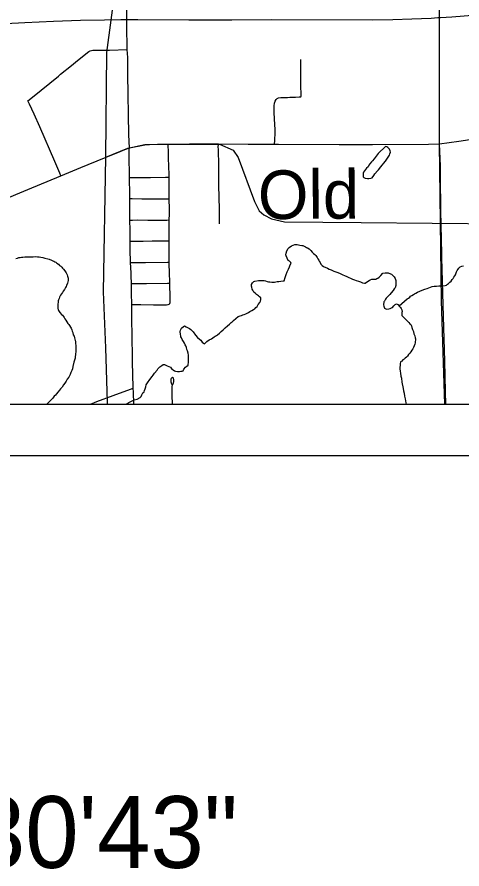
# Model space of a CAD drawing. Extents: x 0 to 34, y 0 to 22.
# Drawn here: x 6.813 to 7.681, y 13.194 to 14.854 of the extents above; entities that cross this region are included whole.
import ezdxf

# ---------------------------------------------------------------- set-up
doc = ezdxf.new("R2010")
doc.units = 0
for name, color, linetype in [('GM_X_City_Street', 7, 'Continuous'), ('GM_X_Corporation', 7, 'Continuous'), ('GM_X_County_Road', 7, 'Continuous'), ('GM_X_Interstate_Route', 7, 'Continuous'), ('GM_X_Minor_Lake', 7, 'Continuous'), ('GM_X_Minor_River', 7, 'Continuous'), ('GM_X_Minor_River_Text', 7, 'Continuous'), ('GM_X_Rail_Line', 7, 'Continuous'), ('GM_X_State_Route', 7, 'Continuous'), ('GM_X_Township_Road', 7, 'Continuous'), ('SH_Data', 7, 'Continuous'), ('SH_Text', 7, 'Continuous')]:
    doc.layers.add(name, color=color, linetype=linetype)

msp = doc.modelspace()

# ---------------------------------------------------------------- linework, layer by layer
at = {"layer": 'GM_X_City_Street'}
for points in [[(6.8345, 14.6908), (6.8433, 14.6982), (6.8942, 14.7392), (6.8984, 14.7429), (6.9194, 14.7598), (6.9314, 14.7696), (6.9434, 14.7796), (6.9506, 14.7854), (6.9531, 14.787), (6.9557, 14.7882), (6.9582, 14.789), (6.9609, 14.7896), (6.9639, 14.7899), (6.9893, 14.7899), (6.9933, 14.7899), (7.028, 14.7908)], [(7.3155, 14.6063), (7.3157, 14.614), (7.3163, 14.6296), (7.3162, 14.6354), (7.3158, 14.645), (7.3148, 14.6679), (7.3146, 14.6743), (7.3148, 14.6779), (7.3146, 14.6813), (7.3151, 14.6868), (7.3164, 14.6905), (7.3184, 14.6934), (7.3204, 14.6954), (7.3232, 14.6967), (7.3276, 14.6977), (7.3406, 14.6978), (7.3448, 14.6979), (7.3517, 14.6981), (7.3564, 14.6984), (7.3634, 14.6987), (7.3654, 14.6988), (7.3663, 14.699), (7.3671, 14.6999), (7.3671, 14.7022), (7.3667, 14.7217), (7.3665, 14.75), (7.3667, 14.7715)], [(6.8986, 14.5448), (6.8965, 14.5499), (6.8873, 14.5728), (6.858, 14.6401), (6.8468, 14.6652), (6.8377, 14.6846), (6.8345, 14.6908)], [(7.0323, 14.5995), (7.0624, 14.605), (7.0717, 14.6059), (7.0872, 14.6066), (7.1079, 14.6067), (7.1119, 14.6069), (7.1492, 14.607), (7.1926, 14.607), (7.2059, 14.6072), (7.2636, 14.6066), (7.3155, 14.6063), (7.3228, 14.6063), (7.4411, 14.6057), (7.5065, 14.606), (7.6155, 14.6069), (7.6368, 14.607)], [(7.1109, 14.2958), (7.1115, 14.2963), (7.1118, 14.2983), (7.1121, 14.3065), (7.1111, 14.3356), (7.1111, 14.3406), (7.1107, 14.3527), (7.1102, 14.3769), (7.1101, 14.4019), (7.1097, 14.4183), (7.1098, 14.4305), (7.1101, 14.4544), (7.1101, 14.4589), (7.1106, 14.4701), (7.1104, 14.4885), (7.1102, 14.4916), (7.11, 14.5001), (7.1096, 14.5315), (7.1098, 14.5422), (7.1091, 14.5684), (7.1087, 14.5745), (7.1088, 14.5774), (7.1084, 14.5956), (7.1081, 14.6005), (7.1079, 14.6067)], [(7.2081, 14.4516), (7.2077, 14.4796), (7.2069, 14.5262), (7.2065, 14.551), (7.2065, 14.5725), (7.2061, 14.5881), (7.2061, 14.5973), (7.2057, 14.6003), (7.2059, 14.6072)], [(7.0324, 14.5415), (7.0367, 14.5417), (7.0429, 14.5417), (7.0621, 14.5415), (7.0736, 14.5416), (7.1028, 14.5421), (7.1098, 14.5422)], [(7.0334, 14.5005), (7.038, 14.5004), (7.0567, 14.5), (7.082, 14.5), (7.1009, 14.4998), (7.104, 14.4999), (7.11, 14.5001)], [(7.0335, 14.4585), (7.0383, 14.4586), (7.0477, 14.4588), (7.0685, 14.4587), (7.1053, 14.4587), (7.1101, 14.4589)], [(7.0339, 14.4176), (7.0452, 14.4176), (7.0591, 14.4178), (7.0766, 14.4179), (7.0973, 14.418), (7.1032, 14.418), (7.1097, 14.4183)], [(7.0348, 14.3758), (7.0393, 14.3758), (7.0477, 14.3757), (7.0637, 14.3761), (7.1068, 14.3768), (7.1102, 14.3769)], [(7.0364, 14.3349), (7.0417, 14.335), (7.066, 14.3353), (7.1068, 14.3357), (7.1111, 14.3356)], [(7.0369, 14.2941), (7.0544, 14.2939), (7.0793, 14.2937), (7.1009, 14.2937), (7.1048, 14.2937), (7.1082, 14.2941), (7.1097, 14.2949), (7.1109, 14.2958)], [(7.1162, 14.1), (7.1159, 14.1171), (7.1159, 14.121), (7.1158, 14.1313), (7.1157, 14.1342), (7.1159, 14.1358), (7.1163, 14.1371), (7.1168, 14.1384), (7.1176, 14.1396), (7.1182, 14.1407), (7.1186, 14.1422), (7.1188, 14.1435), (7.119, 14.1447), (7.119, 14.1466), (7.1189, 14.1478), (7.1186, 14.1493), (7.1182, 14.1504), (7.1175, 14.1511), (7.1167, 14.1515), (7.1157, 14.1515), (7.1148, 14.1512), (7.1139, 14.1497), (7.1134, 14.1485), (7.1131, 14.1459), (7.1133, 14.1434), (7.1139, 14.1413), (7.1157, 14.1369)], [(6.9564, 14.1), (6.9564, 14.1), (6.9691, 14.1049), (7.0009, 14.1169), (7.0348, 14.1293), (7.0399, 14.1312)]]:
    msp.add_lwpolyline(points, dxfattribs=at)
at = {"layer": 'GM_X_Corporation'}
for points in [[(2.1, 20.7089), (2.1, 14.1), (8.9, 14.1), (8.9, 18.9067)], [(4.4234, 14.8562), (4.4253, 14.7443), (4.427, 14.6635), (4.4269, 14.6591), (4.4274, 14.64), (4.4276, 14.6307), (4.4279, 14.6184), (4.4282, 14.6082), (4.4282, 14.5944), (4.4285, 14.5905), (4.4301, 14.5114), (4.431, 14.4741), (4.4318, 14.4347), (4.4315, 14.4227), (4.4317, 14.396), (4.4325, 14.3733), (4.4327, 14.3684), (4.4332, 14.3373), (4.4348, 14.2876), (4.437, 14.154), (4.4374, 14.1), (8.9, 14.1), (8.9, 16.8293)], [(6.7156, 14.1), (7.647, 14.1), (7.6409, 14.3012), (7.6366, 14.6076), (7.6366, 14.6138), (7.6361, 15.1959)]]:
    msp.add_lwpolyline(points, dxfattribs=at)
at = {"layer": 'GM_X_County_Road'}
msp.add_lwpolyline([(7.6368, 14.607), (7.6745, 14.6126), (7.7554, 14.6246)], dxfattribs=at)
at = {"layer": 'GM_X_Interstate_Route'}
for points in [[(7.6338, 14.8533), (7.6358, 14.8534), (7.6388, 14.8536), (7.6607, 14.855), (7.7165, 14.8596), (7.8392, 14.8704), (7.8558, 14.8719), (8.088, 14.8919), (8.2739, 14.9088)], [(6.5624, 14.8184), (6.5714, 14.8197), (6.6176, 14.826), (6.6919, 14.8335), (6.7291, 14.8369), (6.791, 14.8417), (6.8283, 14.844), (6.8842, 14.8465), (6.937, 14.8484), (6.9836, 14.8492), (7.0155, 14.8493)], [(7.0155, 14.8493), (7.0274, 14.8494), (7.0488, 14.8495), (7.1483, 14.8492), (7.2322, 14.8491), (7.3098, 14.8494), (7.5056, 14.8491), (7.546, 14.8496), (7.5832, 14.8507), (7.6205, 14.8524), (7.6338, 14.8533)]]:
    msp.add_lwpolyline(points, dxfattribs=at)
at = {"layer": 'GM_X_Minor_Lake'}
for points in [[(7.5315, 14.6022), (7.5174, 14.5884)], [(7.5311, 14.573), (7.5316, 14.5737), (7.5331, 14.5756), (7.5343, 14.5776), (7.5369, 14.5814), (7.5395, 14.5852), (7.5402, 14.5879), (7.541, 14.5913), (7.5409, 14.5936), (7.5394, 14.597), (7.5363, 14.6), (7.5344, 14.6011), (7.5317, 14.6023), (7.5315, 14.6022)], [(7.5174, 14.5884), (7.5114, 14.5807), (7.5095, 14.5781), (7.5062, 14.5738), (7.5043, 14.5719), (7.5013, 14.5685), (7.499, 14.5658), (7.4975, 14.5627), (7.4945, 14.5596), (7.4926, 14.557), (7.4908, 14.5543), (7.4889, 14.5523), (7.4881, 14.5504), (7.4878, 14.5478), (7.4882, 14.5432), (7.4894, 14.5413), (7.492, 14.5402), (7.4966, 14.5399), (7.4989, 14.5399), (7.5031, 14.5403), (7.5053, 14.5411), (7.5087, 14.5453), (7.511, 14.5488), (7.5162, 14.5549), (7.5177, 14.5568), (7.5226, 14.5626), (7.5311, 14.573)]]:
    msp.add_lwpolyline(points, dxfattribs=at)
at = {"layer": 'GM_X_Minor_River'}
for points in [[(7.2918, 14.3406), (7.2949, 14.3407), (7.2975, 14.3399), (7.3006, 14.3392), (7.3032, 14.3385), (7.3063, 14.3381), (7.3097, 14.3378), (7.3128, 14.3378), (7.3154, 14.3378), (7.3181, 14.3382), (7.3204, 14.3387), (7.3234, 14.3391), (7.3276, 14.3395), (7.3321, 14.3399), (7.334, 14.3403), (7.3359, 14.3468), (7.3377, 14.3525), (7.3399, 14.3579), (7.3422, 14.3629), (7.3444, 14.3674), (7.3459, 14.3716), (7.3474, 14.3743), (7.3473, 14.3762), (7.3443, 14.3785), (7.342, 14.3796), (7.3397, 14.3845), (7.3381, 14.3887), (7.3373, 14.391), (7.3377, 14.3944), (7.3395, 14.399), (7.3418, 14.4032), (7.3436, 14.4055), (7.3482, 14.4082), (7.3519, 14.4098), (7.355, 14.4109), (7.3573, 14.4113), (7.3592, 14.411), (7.3618, 14.4106), (7.3649, 14.4099), (7.3687, 14.4092), (7.3706, 14.4088), (7.374, 14.4073), (7.3759, 14.4066), (7.3778, 14.4055), (7.3797, 14.4047), (7.3828, 14.4025), (7.3859, 14.3991), (7.3886, 14.3964), (7.3913, 14.3938), (7.3936, 14.3915), (7.3955, 14.3897), (7.397, 14.3878), (7.3982, 14.3859), (7.3997, 14.3829), (7.4013, 14.3802), (7.4024, 14.3783), (7.4044, 14.3757), (7.4055, 14.373), (7.4082, 14.3704), (7.4109, 14.3681), (7.4182, 14.3648), (7.422, 14.3629), (7.4258, 14.3614), (7.4311, 14.3588), (7.4384, 14.3566), (7.443, 14.3548), (7.4456, 14.3533), (7.4487, 14.3522), (7.4518, 14.3507), (7.456, 14.3484), (7.4602, 14.3466), (7.4636, 14.3451), (7.4674, 14.3436), (7.4712, 14.3421), (7.4747, 14.341), (7.4792, 14.3396), (7.4827, 14.3381), (7.4865, 14.3366), (7.4903, 14.3359), (7.4922, 14.3355), (7.4964, 14.3386), (7.4994, 14.3409), (7.5016, 14.3421), (7.5047, 14.3433), (7.5081, 14.3437), (7.5107, 14.3437), (7.513, 14.3437), (7.5149, 14.3445), (7.5168, 14.3453), (7.5194, 14.3476), (7.5225, 14.3507), (7.5262, 14.3553), (7.5311, 14.3561), (7.5342, 14.3561), (7.5365, 14.3561), (7.5411, 14.3539), (7.543, 14.3532), (7.5453, 14.3513), (7.5483, 14.3479), (7.5506, 14.3449), (7.5518, 14.3407)], [(6.8113, 14.3839), (6.8143, 14.3847), (6.817, 14.3855), (6.8192, 14.3859), (6.8219, 14.3863), (6.8246, 14.3863), (6.8287, 14.3868), (6.8333, 14.3868), (6.8382, 14.3872), (6.8451, 14.3873), (6.8493, 14.3874), (6.8531, 14.387), (6.8565, 14.3867), (6.8599, 14.3863), (6.8637, 14.3856), (6.8675, 14.3845), (6.8736, 14.3831), (6.8763, 14.3823), (6.8805, 14.3805), (6.8832, 14.3793), (6.8851, 14.3786), (6.887, 14.3775), (6.8889, 14.3764), (6.8912, 14.3749), (6.8939, 14.3726), (6.8962, 14.3704), (6.8985, 14.3685), (6.9004, 14.367), (6.9023, 14.3651), (6.9039, 14.3632), (6.9066, 14.3594), (6.9081, 14.3575), (6.9093, 14.3556), (6.9108, 14.3522), (6.9116, 14.3496), (6.9124, 14.3473), (6.9128, 14.3454), (6.9128, 14.3431), (6.9128, 14.3409), (6.9125, 14.3382), (6.9117, 14.3355), (6.911, 14.3336), (6.9099, 14.3317), (6.9091, 14.3294), (6.908, 14.3271), (6.9058, 14.3233), (6.9032, 14.3198), (6.9017, 14.3175), (6.9002, 14.3148), (6.8979, 14.3125), (6.8964, 14.3087), (6.8953, 14.306), (6.8942, 14.303), (6.8938, 14.3011), (6.8935, 14.2977), (6.8931, 14.2954), (6.8928, 14.2889), (6.8928, 14.287), (6.8936, 14.284), (6.894, 14.2821), (6.8967, 14.2783), (6.8998, 14.2749), (6.9017, 14.2734), (6.904, 14.2704), (6.9052, 14.2685), (6.9067, 14.2662), (6.9083, 14.2636), (6.9106, 14.2602), (6.9125, 14.2571), (6.9145, 14.2549), (6.9156, 14.253), (6.9175, 14.2496)], [(7.558, 14.2912), (7.5739, 14.3052), (7.5761, 14.3067), (7.5788, 14.3086), (7.5806, 14.3102), (7.5829, 14.3117), (7.5859, 14.3137), (7.5882, 14.3148), (7.5908, 14.3164), (7.5942, 14.3183), (7.5988, 14.3203), (7.6033, 14.3222), (7.6083, 14.3238), (7.6128, 14.3254), (7.6162, 14.3265), (7.6192, 14.3277), (7.6223, 14.3289), (7.6261, 14.3297), (7.631, 14.3301), (7.6352, 14.3302), (7.6394, 14.3302), (7.6439, 14.3306), (7.6481, 14.3311), (7.6504, 14.3315), (7.6523, 14.3334), (7.6545, 14.3353), (7.6572, 14.3376), (7.6594, 14.3395), (7.6613, 14.343), (7.6635, 14.3449), (7.665, 14.3476), (7.6665, 14.3499), (7.6677, 14.3518), (7.6688, 14.3537), (7.6695, 14.3556), (7.6699, 14.3575), (7.6714, 14.3602), (7.6729, 14.3629), (7.6747, 14.3652), (7.6774, 14.3675), (7.6804, 14.3687), (7.6838, 14.3695)], [(7.1179, 14.1665), (7.1206, 14.165), (7.1225, 14.1642), (7.126, 14.1635), (7.1279, 14.1635), (7.1298, 14.1635), (7.1324, 14.164), (7.1351, 14.1644), (7.137, 14.1648), (7.1385, 14.1678), (7.1418, 14.1717), (7.1452, 14.1747), (7.1471, 14.1755), (7.1474, 14.1831), (7.1478, 14.1885), (7.1477, 14.1907), (7.1473, 14.1953), (7.1469, 14.1995), (7.1457, 14.204), (7.1445, 14.2063), (7.1437, 14.2105), (7.1422, 14.2135), (7.141, 14.2154), (7.1395, 14.2188), (7.1379, 14.2218), (7.1352, 14.226), (7.134, 14.229), (7.1329, 14.2309), (7.1325, 14.2332), (7.1317, 14.2355), (7.1316, 14.2416), (7.132, 14.2442), (7.1342, 14.2481), (7.1376, 14.2515), (7.1399, 14.2527), (7.1429, 14.2508), (7.1472, 14.2486), (7.1498, 14.2471), (7.1521, 14.2456), (7.1548, 14.2426), (7.1564, 14.2407), (7.161, 14.2343), (7.1652, 14.2297), (7.169, 14.2264), (7.1713, 14.2245), (7.174, 14.2207), (7.1767, 14.2184), (7.179, 14.2177), (7.1835, 14.2219), (7.1881, 14.225), (7.1922, 14.2274), (7.1952, 14.2289), (7.1975, 14.2308), (7.1998, 14.2324), (7.202, 14.2335), (7.2043, 14.2351), (7.2077, 14.2382), (7.2111, 14.2413), (7.2149, 14.2447), (7.219, 14.2486), (7.2235, 14.2524), (7.2277, 14.2559), (7.2307, 14.259), (7.2329, 14.2605), (7.2356, 14.2632), (7.2446, 14.2705), (7.248, 14.2721), (7.2511, 14.2729), (7.2537, 14.2737), (7.256, 14.2744), (7.2594, 14.276), (7.2617, 14.2772), (7.2643, 14.2787), (7.2673, 14.2803), (7.2707, 14.2822), (7.2745, 14.2845), (7.2768, 14.2857), (7.279, 14.288), (7.2813, 14.2903), (7.2835, 14.2941), (7.2865, 14.298), (7.2877, 14.3003), (7.2884, 14.3041), (7.2884, 14.3071), (7.2861, 14.309), (7.2838, 14.3113), (7.2818, 14.3124), (7.2799, 14.3139), (7.2772, 14.3161), (7.2749, 14.3184), (7.273, 14.3218), (7.2718, 14.3237), (7.2707, 14.3279), (7.2703, 14.3301), (7.2706, 14.3328), (7.2721, 14.3366), (7.2747, 14.3386), (7.2766, 14.3397), (7.2842, 14.3409), (7.288, 14.341), (7.2918, 14.3406)], [(7.5518, 14.3407), (7.5519, 14.3377), (7.5519, 14.335), (7.5515, 14.3327), (7.5515, 14.3308), (7.5501, 14.3266), (7.5482, 14.3243), (7.5463, 14.3216), (7.5426, 14.3166), (7.5403, 14.3139), (7.5354, 14.3089), (7.5328, 14.3066), (7.5313, 14.3047), (7.5294, 14.3009), (7.5283, 14.299), (7.5276, 14.2936), (7.528, 14.2906), (7.5296, 14.2872), (7.5338, 14.285), (7.5379, 14.2858), (7.5406, 14.2862), (7.5432, 14.2873), (7.5451, 14.2885), (7.5478, 14.2916), (7.5504, 14.2939), (7.553, 14.2954), (7.5557, 14.2939), (7.5588, 14.2902), (7.5611, 14.2883), (7.5623, 14.2864), (7.5634, 14.2834), (7.5638, 14.2803), (7.5635, 14.2784), (7.5631, 14.2758), (7.5632, 14.2727), (7.5662, 14.2701), (7.5678, 14.2682), (7.577, 14.2588), (7.5793, 14.2565), (7.5812, 14.2554), (7.582, 14.2524), (7.5832, 14.249), (7.5843, 14.2452), (7.5859, 14.2414), (7.5867, 14.2372), (7.5882, 14.2346), (7.5886, 14.2327), (7.5894, 14.2292), (7.5898, 14.227), (7.5899, 14.2243), (7.5895, 14.222), (7.5892, 14.2193), (7.5888, 14.2167), (7.5877, 14.2136), (7.5862, 14.2106), (7.5847, 14.2075), (7.5828, 14.2048), (7.581, 14.2021), (7.5787, 14.1991), (7.5765, 14.1964), (7.5746, 14.1937), (7.5723, 14.1914), (7.5701, 14.1895), (7.5678, 14.1875), (7.5652, 14.186), (7.5633, 14.1837), (7.561, 14.1825), (7.5603, 14.1783), (7.5599, 14.1757), (7.5596, 14.1715), (7.5596, 14.1684), (7.5601, 14.1642), (7.5609, 14.1601), (7.5617, 14.1544), (7.5625, 14.1506), (7.5629, 14.1479), (7.5633, 14.1453), (7.5637, 14.1426), (7.5661, 14.1301), (7.5669, 14.1259), (7.5677, 14.1213), (7.5689, 14.1153), (7.5697, 14.1103), (7.5705, 14.1061), (7.5713, 14.1024), (7.572, 14.1)], [(6.9175, 14.2496), (6.9187, 14.2477), (6.9199, 14.245), (6.921, 14.2424), (6.9218, 14.2394), (6.923, 14.2352), (6.9246, 14.2322), (6.9254, 14.2291), (6.9261, 14.2268), (6.9269, 14.2242), (6.9273, 14.2223), (6.9273, 14.2196), (6.9274, 14.2174), (6.9278, 14.2151), (6.9278, 14.2124), (6.9278, 14.2097), (6.9279, 14.2048), (6.9279, 14.2014), (6.9276, 14.1983), (6.9272, 14.196), (6.9269, 14.193), (6.9265, 14.1896), (6.9254, 14.1858), (6.9243, 14.1816), (6.9221, 14.1732), (6.9214, 14.169), (6.9199, 14.1655), (6.9184, 14.1613), (6.9166, 14.1575), (6.914, 14.1525), (6.9113, 14.1487), (6.9091, 14.1449), (6.9068, 14.141), (6.9042, 14.1372), (6.9012, 14.133), (6.8982, 14.1295), (6.896, 14.1269), (6.893, 14.123), (6.8903, 14.1199), (6.8881, 14.1173), (6.8858, 14.1153), (6.8843, 14.1134), (6.8824, 14.1111), (6.8798, 14.108), (6.8776, 14.1057), (6.8757, 14.1042), (6.8738, 14.1023), (6.8712, 14.1)], [(7.0258, 14.1), (7.0277, 14.1012), (7.0338, 14.1043), (7.0417, 14.1082), (7.0474, 14.1098), (7.0531, 14.1125), (7.055, 14.1148), (7.0569, 14.1179), (7.0587, 14.1217), (7.061, 14.124), (7.0621, 14.1267), (7.0632, 14.1294), (7.0636, 14.1317), (7.0643, 14.1336), (7.065, 14.1374), (7.0676, 14.1412), (7.0691, 14.1431), (7.0706, 14.1462), (7.074, 14.1504), (7.077, 14.1539), (7.0785, 14.1562), (7.0811, 14.16), (7.0864, 14.1661), (7.0879, 14.1688), (7.0898, 14.1707), (7.0917, 14.1727), (7.0954, 14.1754), (7.0981, 14.1769), (7.1007, 14.1773), (7.1061, 14.1747), (7.1095, 14.1732), (7.1122, 14.1717), (7.1153, 14.1683), (7.1179, 14.1665)]]:
    msp.add_lwpolyline(points, dxfattribs=at)
at = {"layer": 'GM_X_Rail_Line'}
for points in [[(6.9864, 14.5814), (6.9881, 14.7854), (7.0056, 14.912), (7.0171, 14.9895), (7.0235, 15.125), (7.0175, 15.4278), (7.0124, 15.7959), (7.0086, 16.0468), (7.0001, 16.5307)], [(6.9864, 14.5814), (7.029, 14.5989), (7.0627, 14.6057), (7.2079, 14.6065), (7.2345, 14.5949), (7.2447, 14.5804), (7.276, 14.4949), (7.2856, 14.4769), (7.2941, 14.4691), (7.3091, 14.4612), (7.3344, 14.4552), (7.4842, 14.454), (7.8993, 14.4498), (8.4402, 14.4462), (8.9, 14.4434)], [(6.9898, 14.1), (6.9894, 14.1038), (6.9862, 14.2097), (6.9816, 14.3187), (6.9864, 14.5814)]]:
    msp.add_lwpolyline(points, dxfattribs=at)
at = {"layer": 'GM_X_State_Route'}
for points in [[(7.0275, 14.842), (7.0274, 14.8494), (7.0272, 14.8642), (7.027, 14.8844), (7.0261, 14.9313)], [(7.0322, 14.5965), (7.0323, 14.5995), (7.0313, 14.6251), (7.0295, 14.7428), (7.029, 14.7757), (7.028, 14.7908), (7.0276, 14.8378), (7.0275, 14.842)], [(7.0401, 14.1232), (7.0399, 14.1312), (7.0391, 14.1589), (7.0387, 14.1803), (7.0385, 14.1927), (7.0373, 14.2682), (7.0372, 14.28), (7.037, 14.2889), (7.0369, 14.2941), (7.0366, 14.3164), (7.0363, 14.3293), (7.0364, 14.3349), (7.0365, 14.3373), (7.036, 14.3475), (7.0356, 14.3556), (7.0348, 14.3758), (7.0338, 14.4016), (7.0339, 14.4176), (7.034, 14.4269), (7.0338, 14.4391), (7.0335, 14.4585), (7.0335, 14.4676), (7.0334, 14.5005), (7.0333, 14.5081), (7.0324, 14.5415), (7.0319, 14.5857), (7.0322, 14.5965)], [(7.0407, 14.1), (7.0407, 14.1004), (7.0401, 14.1232)]]:
    msp.add_lwpolyline(points, dxfattribs=at)
at = {"layer": 'GM_X_Township_Road'}
for points in [[(6.984, 14.5798), (7.0097, 14.5903), (7.0233, 14.596), (7.0323, 14.5995)], [(7.6492, 14.1), (7.6484, 14.1246), (7.6471, 14.1836), (7.6446, 14.2705), (7.6415, 14.3853), (7.6404, 14.4287), (7.6401, 14.441), (7.64, 14.4503), (7.6396, 14.4751), (7.6394, 14.4875), (7.6393, 14.5028), (7.6388, 14.5183), (7.639, 14.5285), (7.6386, 14.5471), (7.6385, 14.5681), (7.6384, 14.5743), (7.6384, 14.5789), (7.6368, 14.607)], [(6.8986, 14.5448), (6.938, 14.561), (6.984, 14.5798)], [(6.7325, 14.4775), (6.7428, 14.4806), (6.783, 14.4971), (6.8344, 14.5185), (6.8986, 14.5448)]]:
    msp.add_lwpolyline(points, dxfattribs=at)
at = {"layer": 'SH_Data'}
for p, q in [((2.1, 14.1), (8.9, 14.1)), ((2, 14), (9, 14))]:
    msp.add_line(p, q, dxfattribs=at)

# ---------------------------------------------------------------- texts
at = {"layer": 'GM_X_Minor_River_Text'}
msp.add_text('Old', height=0.09475, rotation=0.3609, dxfattribs=at).set_placement((7.2831, 14.4604))
at = {"layer": 'SH_Text'}
msp.add_text('LATITUDE:  41°22\'01"     LONGITUDE:  82°30\'43"', height=0.14, dxfattribs=at).set_placement((3.071, 13.1959))

doc.saveas('drawing.dxf')
